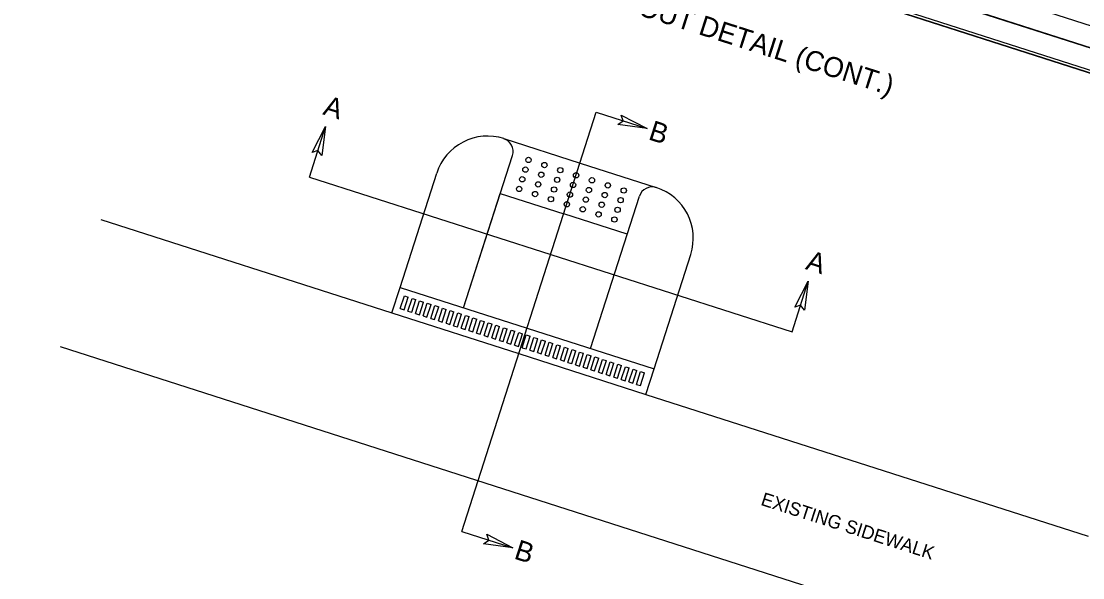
# Model space of a CAD drawing. Extents: x 928111 to 937215, y 684320 to 686530.
# Drawn here: x 933630.93 to 933670.73, y 684674.31 to 684695.17 of the extents above; entities that cross this region are included whole.
import ezdxf

# ---------------------------------------------------------------- set-up
doc = ezdxf.new("R2010")
doc.units = 0
for name, color, linetype in [('Exist Roads EOP', 7, 'Continuous'), ('Prop Conc 5in Monolithic Keyed In Island', 7, 'Continuous'), ('Prop Conc Curb 8in x 6in', 7, 'Continuous'), ('Prop Dimension', 7, 'Continuous'), ('Prop DSN Text', 7, 'Continuous'), ('Prop Terminator CELL', 7, 'Continuous'), ('Sheet Clip Boundary CELL', 7, 'Continuous'), ('Sheet Cutting Line CELL', 7, 'Continuous'), ('Sheet Layout Plan Border', 7, 'Continuous'), ('Sheet Plan CELL', 7, 'Continuous'), ('Sheet Plan Layout CELL', 7, 'Continuous'), ('Sheet Plot Border Inside CELL', 7, 'Continuous'), ('Sheet Plot Border Outside CELL', 7, 'Continuous')]:
    doc.layers.add(name, color=color, linetype=linetype)

msp = doc.modelspace()

# ---------------------------------------------------------------- linework, layer by layer
at = {"layer": 'Exist Roads EOP'}
for p, q in [((933633.915, 684687.734), (933644.828, 684684.236)), ((933632.389, 684682.973), (933669.407, 684671.107)), ((933654.351, 684681.184), (933670.933, 684675.868))]:
    msp.add_line(p, q, dxfattribs=at)
at = {"layer": 'Prop Conc 5in Monolithic Keyed In Island'}
for p, q in [((933647.514, 684684.425), (933649.346, 684690.139)), ((933645.134, 684685.188), (933646.507, 684689.474)), ((933647.514, 684684.425), (933648.888, 684688.71)), ((933652.276, 684682.899), (933654.107, 684688.613)), ((933654.656, 684682.136), (933656.03, 684686.421)), ((933644.828, 684684.236), (933645.134, 684685.188)), ((933645.143, 684684.398), (933645.295, 684684.874)), ((933645.286, 684684.352), (933645.438, 684684.828)), ((933645.295, 684684.874), (933645.438, 684684.828)), ((933645.428, 684684.306), (933645.581, 684684.782)), ((933645.571, 684684.26), (933645.724, 684684.737)), ((933645.581, 684684.782), (933645.724, 684684.737)), ((933645.143, 684684.398), (933645.286, 684684.352)), ((933645.714, 684684.215), (933645.867, 684684.691)), ((933645.857, 684684.169), (933646.01, 684684.645)), ((933645.867, 684684.691), (933646.01, 684684.645)), ((933646, 684684.123), (933646.152, 684684.599)), ((933646.143, 684684.077), (933646.295, 684684.553)), ((933646.152, 684684.599), (933646.295, 684684.553)), ((933646.285, 684684.032), (933646.438, 684684.508)), ((933646.428, 684683.986), (933646.581, 684684.462)), ((933646.438, 684684.508), (933646.581, 684684.462)), ((933646.571, 684683.94), (933646.724, 684684.416)), ((933646.714, 684683.894), (933646.867, 684684.37)), ((933646.724, 684684.416), (933646.867, 684684.37)), ((933646.857, 684683.848), (933647.009, 684684.324)), ((933647.009, 684684.324), (933647.152, 684684.279)), ((933645.428, 684684.306), (933645.571, 684684.26)), ((933645.714, 684684.215), (933645.857, 684684.169)), ((933646, 684684.123), (933646.143, 684684.077)), ((933646.285, 684684.032), (933646.428, 684683.986)), ((933646.571, 684683.94), (933646.714, 684683.894)), ((933647, 684683.803), (933647.152, 684684.279)), ((933647.142, 684683.757), (933647.295, 684684.233)), ((933647.285, 684683.711), (933647.438, 684684.187)), ((933647.295, 684684.233), (933647.438, 684684.187)), ((933647.428, 684683.665), (933647.581, 684684.141)), ((933647.571, 684683.619), (933647.724, 684684.096)), ((933647.581, 684684.141), (933647.724, 684684.096)), ((933647.714, 684683.574), (933647.866, 684684.05)), ((933647.857, 684683.528), (933648.009, 684684.004)), ((933647.866, 684684.05), (933648.009, 684684.004)), ((933648, 684683.482), (933648.152, 684683.958)), ((933648.152, 684683.958), (933648.295, 684683.912)), ((933646.857, 684683.848), (933647, 684683.803)), ((933647.142, 684683.757), (933647.285, 684683.711)), ((933647.428, 684683.665), (933647.571, 684683.619)), ((933647.714, 684683.574), (933647.857, 684683.528)), ((933648.142, 684683.436), (933648.295, 684683.912)), ((933648.285, 684683.39), (933648.438, 684683.867)), ((933648.428, 684683.345), (933648.581, 684683.821)), ((933648.438, 684683.867), (933648.581, 684683.821)), ((933648.571, 684683.299), (933648.723, 684683.775)), ((933648.714, 684683.253), (933648.866, 684683.729)), ((933648.723, 684683.775), (933648.866, 684683.729)), ((933648.857, 684683.207), (933649.009, 684683.683)), ((933648.999, 684683.162), (933649.152, 684683.638)), ((933649.009, 684683.683), (933649.152, 684683.638)), ((933649.142, 684683.116), (933649.295, 684683.592)), ((933649.285, 684683.07), (933649.438, 684683.546)), ((933649.295, 684683.592), (933649.438, 684683.546)), ((933648, 684683.482), (933648.142, 684683.436)), ((933648.285, 684683.39), (933648.428, 684683.345)), ((933648.571, 684683.299), (933648.714, 684683.253)), ((933648.857, 684683.207), (933648.999, 684683.162)), ((933649.428, 684683.024), (933649.581, 684683.5)), ((933649.571, 684682.978), (933649.723, 684683.455)), ((933649.581, 684683.5), (933649.723, 684683.455)), ((933649.714, 684682.933), (933649.866, 684683.409)), ((933649.856, 684682.887), (933650.009, 684683.363)), ((933649.866, 684683.409), (933650.009, 684683.363)), ((933649.999, 684682.841), (933650.152, 684683.317)), ((933650.142, 684682.795), (933650.295, 684683.271)), ((933650.152, 684683.317), (933650.295, 684683.271)), ((933650.285, 684682.749), (933650.438, 684683.226)), ((933650.428, 684682.704), (933650.58, 684683.18)), ((933650.438, 684683.226), (933650.58, 684683.18)), ((933650.571, 684682.658), (933650.723, 684683.134)), ((933650.723, 684683.134), (933650.866, 684683.088)), ((933649.142, 684683.116), (933649.285, 684683.07)), ((933649.428, 684683.024), (933649.571, 684682.978)), ((933649.714, 684682.933), (933649.856, 684682.887)), ((933649.999, 684682.841), (933650.142, 684682.795)), ((933650.285, 684682.749), (933650.428, 684682.704)), ((933650.713, 684682.612), (933650.866, 684683.088)), ((933650.856, 684682.566), (933651.009, 684683.042)), ((933650.999, 684682.521), (933651.152, 684682.997)), ((933651.009, 684683.042), (933651.152, 684682.997)), ((933651.142, 684682.475), (933651.295, 684682.951)), ((933651.285, 684682.429), (933651.437, 684682.905)), ((933651.295, 684682.951), (933651.437, 684682.905)), ((933651.428, 684682.383), (933651.58, 684682.859)), ((933651.571, 684682.337), (933651.723, 684682.814)), ((933651.58, 684682.859), (933651.723, 684682.814)), ((933651.713, 684682.292), (933651.866, 684682.768)), ((933651.866, 684682.768), (933652.009, 684682.722)), ((933650.571, 684682.658), (933650.713, 684682.612)), ((933650.856, 684682.566), (933650.999, 684682.521)), ((933651.142, 684682.475), (933651.285, 684682.429)), ((933651.428, 684682.383), (933651.571, 684682.337)), ((933651.856, 684682.246), (933652.009, 684682.722)), ((933651.999, 684682.2), (933652.152, 684682.676)), ((933652.142, 684682.154), (933652.295, 684682.63)), ((933652.152, 684682.676), (933652.295, 684682.63)), ((933652.285, 684682.108), (933652.437, 684682.585)), ((933652.428, 684682.063), (933652.58, 684682.539)), ((933652.437, 684682.585), (933652.58, 684682.539)), ((933652.57, 684682.017), (933652.723, 684682.493)), ((933652.713, 684681.971), (933652.866, 684682.447)), ((933652.723, 684682.493), (933652.866, 684682.447)), ((933652.856, 684681.925), (933653.009, 684682.401)), ((933652.999, 684681.88), (933653.152, 684682.356)), ((933653.009, 684682.401), (933653.152, 684682.356)), ((933651.713, 684682.292), (933651.856, 684682.246)), ((933651.999, 684682.2), (933652.142, 684682.154)), ((933652.285, 684682.108), (933652.428, 684682.063)), ((933652.57, 684682.017), (933652.713, 684681.971)), ((933653.142, 684681.834), (933653.294, 684682.31)), ((933653.285, 684681.788), (933653.437, 684682.264)), ((933653.294, 684682.31), (933653.437, 684682.264)), ((933653.427, 684681.742), (933653.58, 684682.218)), ((933653.57, 684681.696), (933653.723, 684682.173)), ((933653.58, 684682.218), (933653.723, 684682.173)), ((933653.713, 684681.651), (933653.866, 684682.127)), ((933653.856, 684681.605), (933654.009, 684682.081)), ((933653.866, 684682.127), (933654.009, 684682.081)), ((933653.999, 684681.559), (933654.151, 684682.035)), ((933654.142, 684681.513), (933654.294, 684681.989)), ((933654.151, 684682.035), (933654.294, 684681.989)), ((933654.351, 684681.184), (933654.656, 684682.136)), ((933652.856, 684681.925), (933652.999, 684681.88)), ((933653.142, 684681.834), (933653.285, 684681.788)), ((933653.427, 684681.742), (933653.57, 684681.696)), ((933653.713, 684681.651), (933653.856, 684681.605)), ((933653.999, 684681.559), (933654.142, 684681.513))]:
    msp.add_line(p, q, dxfattribs=at)
for centre, start, end in [((933648.412, 684688.863), 72.2273, 162.2273), ((933654.125, 684687.032), 342.2273, 72.2273)]:
    msp.add_arc(centre, 2, start, end, dxfattribs=at)
at = {"layer": 'Prop Conc Curb 8in x 6in'}
for p, q in [((933649.022, 684690.768), (933651.879, 684689.852)), ((933651.879, 684689.852), (933654.736, 684688.936)), ((933648.888, 684688.71), (933651.269, 684687.947)), ((933653.649, 684687.184), (933651.269, 684687.947)), ((933645.134, 684685.188), (933649.895, 684683.662)), ((933644.828, 684684.236), (933649.59, 684682.71)), ((933649.895, 684683.662), (933654.656, 684682.136)), ((933649.59, 684682.71), (933654.351, 684681.184))]:
    msp.add_line(p, q, dxfattribs=at)
for centre in [(933649.947, 684689.969), (933649.831, 684689.606), (933650.426, 684689.416), (933650.543, 684689.778), (933651.138, 684689.587), (933651.733, 684689.396), (933649.715, 684689.244), (933650.31, 684689.053), (933651.022, 684689.225), (933651.617, 684689.034), (933652.328, 684689.206), (933652.923, 684689.015), (933649.599, 684688.882), (933650.194, 684688.691), (933650.906, 684688.863), (933651.501, 684688.672), (933652.212, 684688.843), (933652.807, 684688.653), (933653.518, 684688.824), (933650.789, 684688.5), (933651.385, 684688.31), (933652.096, 684688.481), (933652.691, 684688.29), (933653.402, 684688.462), (933651.98, 684688.119), (933652.575, 684687.928), (933653.286, 684688.1), (933653.17, 684687.737)]:
    msp.add_circle(centre, 0.1, dxfattribs=at)
for centre, start, end in [((933648.87, 684690.291), 342.2273, 72.2273), ((933654.583, 684688.46), 72.2273, 162.2273)]:
    msp.add_arc(centre, 0.5, start, end, dxfattribs=at)
at = {"layer": 'Prop Dimension'}
for p, q in [((933647.453, 684676.044), (933652.489, 684691.756)), ((933652.489, 684691.756), (933654.394, 684691.146)), ((933641.733, 684689.321), (933642.343, 684691.226)), ((933641.733, 684689.321), (933659.826, 684683.522)), ((933659.826, 684683.522), (933660.437, 684685.426)), ((933647.453, 684676.044), (933649.358, 684675.433))]:
    msp.add_line(p, q, dxfattribs=at)
at = {"layer": 'Prop Terminator CELL'}
for points in [[(933653.422, 684691.653), (933654.394, 684691.146), (933653.301, 684691.295), (933653.491, 684691.435)], [(933641.837, 684690.254), (933642.343, 684691.226), (933642.195, 684690.133), (933642.054, 684690.323)], [(933659.93, 684684.455), (933660.437, 684685.426), (933660.288, 684684.334), (933660.147, 684684.524)], [(933648.386, 684675.94), (933649.358, 684675.433), (933648.265, 684675.582), (933648.455, 684675.723)]]:
    msp.add_lwpolyline(points, close=True, dxfattribs=at)
at = {"layer": 'Sheet Clip Boundary CELL'}
msp.add_lwpolyline([(933619.504, 684665.63), (933672.831, 684648.536), (933683.069, 684680.476), (933675.86, 684682.787), (933678.442, 684690.842), (933632.324, 684705.625)], close=True, dxfattribs=at)
at = {"layer": 'Sheet Cutting Line CELL'}
for p, q in [((933624.352, 684709.125), (933688.478, 684688.57)), ((933688.478, 684688.57), (933624.352, 684709.125))]:
    msp.add_line(p, q, dxfattribs=at)
at = {"layer": 'Sheet Layout Plan Border'}
msp.add_lwpolyline([(933619.504, 684665.63), (933672.831, 684648.536), (933683.069, 684680.476), (933675.86, 684682.787), (933678.442, 684690.842), (933632.324, 684705.625)], close=True, dxfattribs=at)
at = {"layer": 'Sheet Plan CELL'}
for points in [[(933687.557, 684687.921), (933630.419, 684706.236), (933617.599, 684666.24), (933674.736, 684647.926)], [(933617.599, 684666.24), (933630.418, 684706.235), (933679.936, 684690.364), (933678.104, 684684.648), (933685.724, 684682.205), (933674.736, 684647.926)]]:
    msp.add_lwpolyline(points, close=True, dxfattribs=at)
at = {"layer": 'Sheet Plan Layout CELL'}
msp.add_lwpolyline([(933630.418, 684706.235), (933617.599, 684666.24), (933674.736, 684647.926), (933684.973, 684679.865), (933675.86, 684682.787), (933678.442, 684690.842)], close=True, dxfattribs=at)
at = {"layer": 'Sheet Plot Border Inside CELL'}
for points in [[(933625.091, 684709.728), (933688.551, 684689.388), (933701.432, 684729.573), (933637.973, 684749.914)], [(933611.722, 684668.018), (933675.181, 684647.678), (933688.063, 684687.863), (933624.603, 684708.204)]]:
    msp.add_lwpolyline(points, close=True, dxfattribs=at)
at = {"layer": 'Sheet Plot Border Outside CELL'}
for points in [[(933624.352, 684709.125), (933688.478, 684688.57), (933701.848, 684730.28), (933637.722, 684750.835)], [(933610.982, 684667.415), (933675.109, 684646.86), (933688.478, 684688.57), (933624.352, 684709.125)]]:
    msp.add_lwpolyline(points, close=True, dxfattribs=at)

# ---------------------------------------------------------------- texts
at = {"layer": 'Prop DSN Text'}
for s, height, p in [('PEDESTRIAN BULBOUT DETAIL (CONT.)', 0.75, (933645.138, 684698.264)), ('A', 0.75, (933642.208, 684691.685)), ('B', 0.75, (933654.406, 684690.749)), ('A', 0.75, (933660.301, 684685.885)), ('EXISTING SIDEWALK ', 0.5, (933658.625, 684677.045)), ('B', 0.75, (933649.369, 684675.037))]:
    msp.add_text(s, height=height, rotation=342.2273, dxfattribs=at).set_placement(p)

doc.saveas('drawing.dxf')
